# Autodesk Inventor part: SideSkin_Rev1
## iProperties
Created: 2008-11
Part Number: SideSkin_Rev1
Document SubType Name: Modeling
Designer: claivier
Norme de conversion: STEP AP214IS
Nom du fichier: SideSkin_Rev1.STEP
Préprocesseur: SolidWorks 2008
Postprocesseur: Build: 344a, Release: 11 SP2 - Date: Fri 08/18/2006
Unités envoyées: INCHES
Incertitude: 1e-05
Author: claivier
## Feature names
1. Base1
